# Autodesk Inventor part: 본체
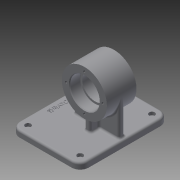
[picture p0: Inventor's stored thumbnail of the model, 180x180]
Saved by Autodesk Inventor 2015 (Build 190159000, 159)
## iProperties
Created: 2019-09
Part Number: 본체
Material: 일반
Document SubType Name: Modeling
Designer: now
Density: 1 g/cm^3
Appearance: 기본값
Mass: 205.415 g
Surface Area: 495.884 cm^2
Volume: 205.415 cm^3
Author: now
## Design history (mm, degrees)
sketch "스케치1"
  geometry: L1 (-49, 63)-(49, 63); L2 (49, 63)-(49, -63); L3 (49, -63)-(-49, -63); L4 (-49, -63)-(-49, 63); L5 (-49, 63)-(49, -63); L6 (49, 63)-(-49, -63); 1 further point
  constraints: 12 end point, 2 midpoint, 2 parallel, 1 horizontal, 1 perpendicular
  dimensions: "d0" = 98 distance of L2.end L3.end; "d1" = 126 distance of L1.end L2.end
extrude "돌출1" new body sketch "스케치1" distance "d2" = 9; taper "d3" = 0 deg
fillet "모깎기1" dims "d4" = 12
sketch "스케치2"
  geometry: A1 r 12 centre (-37, 51) between (-37, 63) and (-49, 51) reference; A2 r 12 centre (-37, -51) between (-49, -51) and (-37, -63) reference; A3 r 12 centre (37, -51) between (37, -63) and (49, -51) reference; A4 r 12 centre (37, 51) between (49, 51) and (37, 63) reference; 1 further point
hole "구멍1" sketch "스케치2" at (37, -51), (-37, -51), (-37, 51), (37, 51) diameter "d5" = 4.5; stored, may be unused: countersink angle "d9" = 90 deg, drill point angle "d11" = 118 deg; dims "d6" = 6, "d7" = 8, "d8" = 4.4, "d10" = 8
sketch "스케치3"
  geometry: L1 (-49, 51)-(-49, -51) reference; L2 (-19, -4)-(45, -4); L3 (45, -4)-(45, 4); L4 (45, 4)-(-19, 4); L5 (-19, 4)-(-19, -4); L6 (-19, -4)-(45, 4); L7 (45, -4)-(-19, 4); 3 further points
  constraints: 12 end point, 3 midpoint, 2 parallel, 1 horizontal, 1 horizontal alignment, 1 perpendicular
  dimensions: "d31" = 62 distance from line of L1 point (13, 0); "d32" = 4 distance from line of point (13, 0) L2; "d33" = 32 distance from line of L5 point (13, 0)
extrude "돌출2" join sketch "스케치3" distance "d15" = 50; taper "d16" = 0 deg
sketch "스케치4"
  geometry: L1 (49, -51)-(49, 51) reference; L2 (9, -17)-(17, -17); L3 (17, -17)-(17, 17); L4 (17, 17)-(9, 17); L5 (9, 17)-(9, -17); L6 (9, -17)-(17, 17); L7 (17, -17)-(9, 17); L8 (49, 51)-(49, -51) reference; 4 further points
  constraints: 12 end point, 4 midpoint, 2 parallel, 1 horizontal, 1 horizontal alignment, 1 perpendicular
  dimensions: "d28" = 36 distance from line of L1 point (13, 0); "d29" = 4 distance from line of L5 point (13, 0); "d30" = 34 distance of L2.end L3.end
extrude "돌출3" join sketch "스케치4" distance "d19" = 50; taper "d20" = 0 deg
fillet "모깎기2" dims "d21" = 3
fillet "모깎기5" dims "d34" = 3
fillet "모깎기6" dims "d35" = 3
sketch "스케치5"
  geometry: L1 (22, 9)-(46, 9) reference; L2 (49, 6)-(49, 0) reference; L3 (49, 0)-(-49, 0) reference; L4 (-49, 0)-(-49, 6) reference; L5 (-45, 11.657)-(-45, 59) reference; L6 (-45, 59)-(19, 59) reference; L7 (19, 59)-(19, 12) reference; C1 r 32 at (-13, 59); A1 r 3 centre (46, 6) between (49, 6) and (46, 9) reference; A2 r 3 centre (-48, 11.657) between (-47, 8.828) and (-45, 11.657) reference; A3 r 3 centre (22, 12) between (19, 12) and (22, 9) reference; A4 r 3 centre (-46, 6) between (-47, 8.828) and (-49, 6) reference; 1 further point
  constraints: 1 centre point
  dimensions: "d24" = 64 diameter of C1; "d25" = 59 distance from line of L3 C1.centre; "d36" = 36 distance from line of C1.centre L4
extrude "돌출4" join sketch "스케치5" stored distance "d26" = 42; taper "d27" = 0 deg
sketch "스케치6"
  geometry: C1 r 32 at (0, 0) reference; C2 r 21 at (0, 0); 1 further point
  constraints: 1 centre point, 1 coincident
  dimensions: "d37" = 42 diameter of C2
extrude "돌출5" cut sketch "스케치6" distance "d38" = 15; taper "d39" = 0 deg
sketch "스케치7"
  geometry: C1 r 32 at (0, 0) reference; C2 r 21 at (0, 0); 1 further point
  constraints: 1 centre point, 1 coincident
  dimensions: "d40" = 42 diameter of C2
extrude "돌출6" cut sketch "스케치7" distance "d41" = 15; taper "d42" = 0 deg
sketch "스케치8"
  geometry: C1 r 21 at (0, 0) reference; C2 r 18 at (0, 0); 1 further point
  constraints: 1 centre point, 1 coincident
  dimensions: "d43" = 36 diameter of C2
extrude "돌출7" cut sketch "스케치8" stored distance "d44" = 15; taper "d45" = 0 deg
fillet "모깎기7" dims "d46" = 0.3
sketch "스케치9"
  geometry: C1 r 21 at (0, 0) reference; 2 further points
  constraints: 1 vertical alignment
  dimensions: "d47" = 26 distance of C1.centre point (0, -26)
hole "구멍2" sketch "스케치9" at (0, -26) diameter "d48" = 3.242; stored, may be unused: countersink angle "d52" = 90 deg, drill point angle "d54" = 118 deg; dims "d49" = 8, "d50" = 4, "d51" = 2, "d53" = 10
chamfer "모따기1" distance "d58" = 1; stored, may be unused: second distance "d59" = 2, angle "d60" = 45 deg
fillet "모깎기8" dims "d61" = 3
sketch "스케치10"
  geometry: L1 (37, 63)-(-37, 63) reference; L2 (-49, -51)-(-49, 51) reference; 2 further points
  constraints: 1 other
  dimensions: "d62" = 63 distance from line of L1 point (-39, 0); "d63" = 10 distance from line of L2 point (-39, 0)
feature "엠보싱1" sketch "스케치10" dims "d0" = 98, "d1" = 126, "d64" = 0.5, "d65" = 0
node "솔리드1"
pattern_circular "원형 패턴1" dims angle "d56" = 360 deg
mirror "대칭1"
node "절단 모서리 투영1"
